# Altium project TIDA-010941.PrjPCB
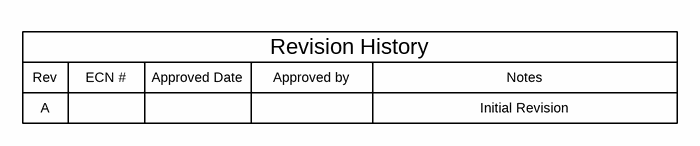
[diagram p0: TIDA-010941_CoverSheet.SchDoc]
CopyrightYear: 2023; PCB_Layout: Boyu Shen; PCB_Rev: E1; PRJ_Customer: Public Release; PRJ_Engineer: Boyu Shen; PRJ_Number: TIDA-010941; PRJ_Title: SASI Smoke Detection w/ Amb. Light Cancellation; SCH_Rev: A; TechSupport: http://www.ti.com/support; TID: TIDA-010941
3 sheets, 116 parts. Net scope: global (net labels, ports and power ports of the same name join across sheets).
Board file: TIDA-010941.PcbDoc
Sheets:
  TIDA-010941_CoverSheet.SchDoc
  TIDA-010941_Hardware.SchDoc
  TIDA-010941_M0L1306.SchDoc

## Sheet TIDA-010941_CoverSheet.SchDoc: Block Diagram / Revision History
size 431 x 279 mm; Date: Not shown in title block; ApprovedBy: Not shown in title block; CheckedBy: Not shown in title block; Author: Not shown in title block; CompanyName: Not shown in title block; DrawnBy: Boyu Shen; Engineer: Not shown in title block; Organization: Not shown in title block; Address1: Not shown in title block; Address2: Not shown in title block; Address3: Not shown in title block; Address4: Not shown in title block; DocumentNumber: 1; Revision: Use project parameter SCH_Rev; SheetNumber: 1; SheetTotal: 3; PageSetup: Record=PageOptions¦CenterHorizontal=True¦CenterVertical=True¦PrintScale=1.00¦XCorrection=1.00¦YCorrection=1.00¦PrintKind=0¦BorderSize=5000000¦LeftOffset=0¦BottomOffset=0¦Orientation=2¦PaperLength=1000¦PaperWidth=1000¦Scale=100¦PaperSource=15¦PrintQuality=600¦MediaType=1¦DitherType=10¦PaperKind=Letter¦PrintScaleMode=1

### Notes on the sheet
- Rev
- A
- ECN #
- Approved Date
- Approved by
- Revision History
- Notes
- Initial Revision

## Sheet TIDA-010941_Hardware.SchDoc: Hardware
size 431 x 279 mm; Date: Not shown in title block; ApprovedBy: Not shown in title block; CheckedBy: Not shown in title block; Author: Not shown in title block; CompanyName: Not shown in title block; DrawnBy: Boyu Shen; Engineer: Not shown in title block; Organization: Not shown in title block; Address1: Not shown in title block; Address2: Not shown in title block; Address3: Not shown in title block; Address4: Not shown in title block; DocumentNumber: 3; Revision: Use project parameter SCH_Rev; SheetNumber: 3; SheetTotal: 3; PageSetup: Record=PageOptions¦CenterHorizontal=True¦CenterVertical=True¦PrintScale=1.00¦XCorrection=1.00¦YCorrection=1.00¦PrintKind=0¦BorderSize=5000000¦LeftOffset=0¦BottomOffset=0¦Orientation=2¦PaperLength=1000¦PaperWidth=1000¦Scale=100¦PaperSource=15¦PrintQuality=600¦MediaType=1¦DitherType=10¦PaperKind=Letter¦PrintScaleMode=1
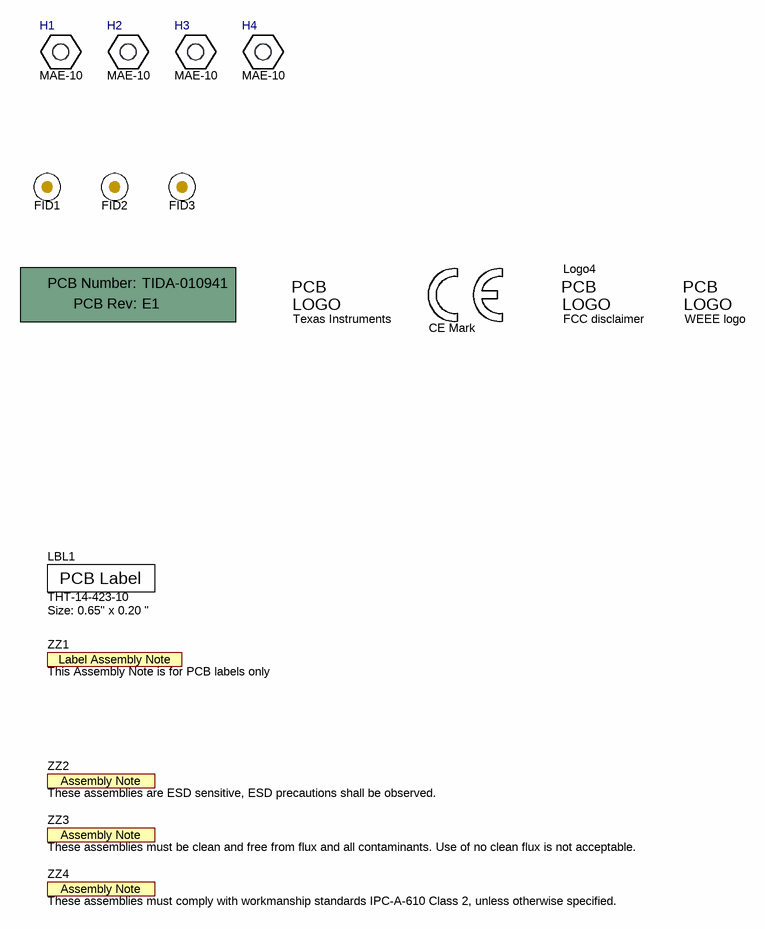
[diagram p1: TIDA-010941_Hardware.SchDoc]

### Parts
!PCB1  Printed Circuit Board  (value not drawn)  (mechanical)
FID1  Fiducial  [Fiducial10-20]  (value not drawn)
FID2  Fiducial  [Fiducial10-20]  (value not drawn)
FID3  Fiducial  [Fiducial10-20]  (value not drawn)
H1  MAE-10  [KY_MAE-10]
H2  MAE-10  [KY_MAE-10]
H3  MAE-10  [KY_MAE-10]
H4  MAE-10  [KY_MAE-10]
LBL1  THT-14-423-10  Note: Size: 0.65" x 0.20 "  [Label_650x200]
Logo1  CE Mark  [CE_Mark_5mm]  (no BOM)
Logo2  Texas Instruments  [TI_Symbol_Overlay_Small]  (no BOM)
Logo3  WEEE logo  [WEEE_Minimum]  (no BOM)
Logo4  FCC disclaimer  [FCC_disclaimer]  (no BOM)
ZZ1  This Assembly Note is for PCB labels only  [AssemblyNoteLabel]  (no BOM)
ZZ2  These assemblies are ESD sensitive, ESD precautions shall be observed.  [AssemblyNote]  (no BOM)
ZZ3  These assemblies must be clean and free from flux and all contaminants. Use of no clean flux is not acceptable.  [AssemblyNote]  (no BOM)
ZZ4  These assemblies must comply with workmanship standards IPC-A-610 Class 2, unless otherwise specified.  [AssemblyNote]  (no BOM)

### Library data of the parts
!PCB1 = CMP-0003618-2: Manufacturer: Any; PartNumber: TIDA-010941
FID1-FID3 = CMP-0077181-1: Fiducial mark.  There is nothing to buy or mount.
H1-H4 = CMP-0077978-1: Spacer Support, Nylon 66; Manufacturer: Kang Yang; CompType: Standoff
LBL1 = CMP-0003625-1: Thermal Transfer Printable Labels, 0.650" W x 0.200" H - 10,000 per roll; Manufacturer: Brady; CompType: Label
Logo1 = CMP-0074844-1: SymbolCreator: a0412235
Logo2 = CMP-0074838-1: Texas Instrument Corporate Signature; SymbolCreator: a0412235; Lib Reference: TI_Logo; Library Reference: Logo
Logo3 = CMP-0074769-1
Logo4 = CMP-0074847-1: FCC_disclaimer
ZZ1 = CMP-0003616-3
ZZ2 = CMP-0077236-1
ZZ3 = CMP-0077237-1
ZZ4 = CMP-0077238-1

## Sheet TIDA-010941_M0L1306.SchDoc: Main Circuit Schematic
size A2; Date: Not shown in title block; ApprovedBy: Not shown in title block; CheckedBy: Not shown in title block; Author: Not shown in title block; CompanyName: Not shown in title block; DrawnBy: Boyu Shen; Engineer: Not shown in title block; Organization: Not shown in title block; Address1: Not shown in title block; Address2: Not shown in title block; Address3: Not shown in title block; Address4: Not shown in title block; DocumentNumber: 1; Revision: Use project parameter SCH_Rev; SheetNumber: 2; SheetTotal: 3; PageSetup: Record=PageOptions¦CenterHorizontal=True¦CenterVertical=True¦PrintScale=0.69¦XCorrection=1.00¦YCorrection=1.00¦PrintKind=0¦BorderSize=5000000¦LeftOffset=0¦BottomOffset=0¦Orientation=2¦PaperLength=1000¦PaperWidth=1000¦Scale=100¦PaperSource=15¦PrintQuality=600¦MediaType=1¦DitherType=10¦PaperKind=Letter¦PrintScaleMode=1
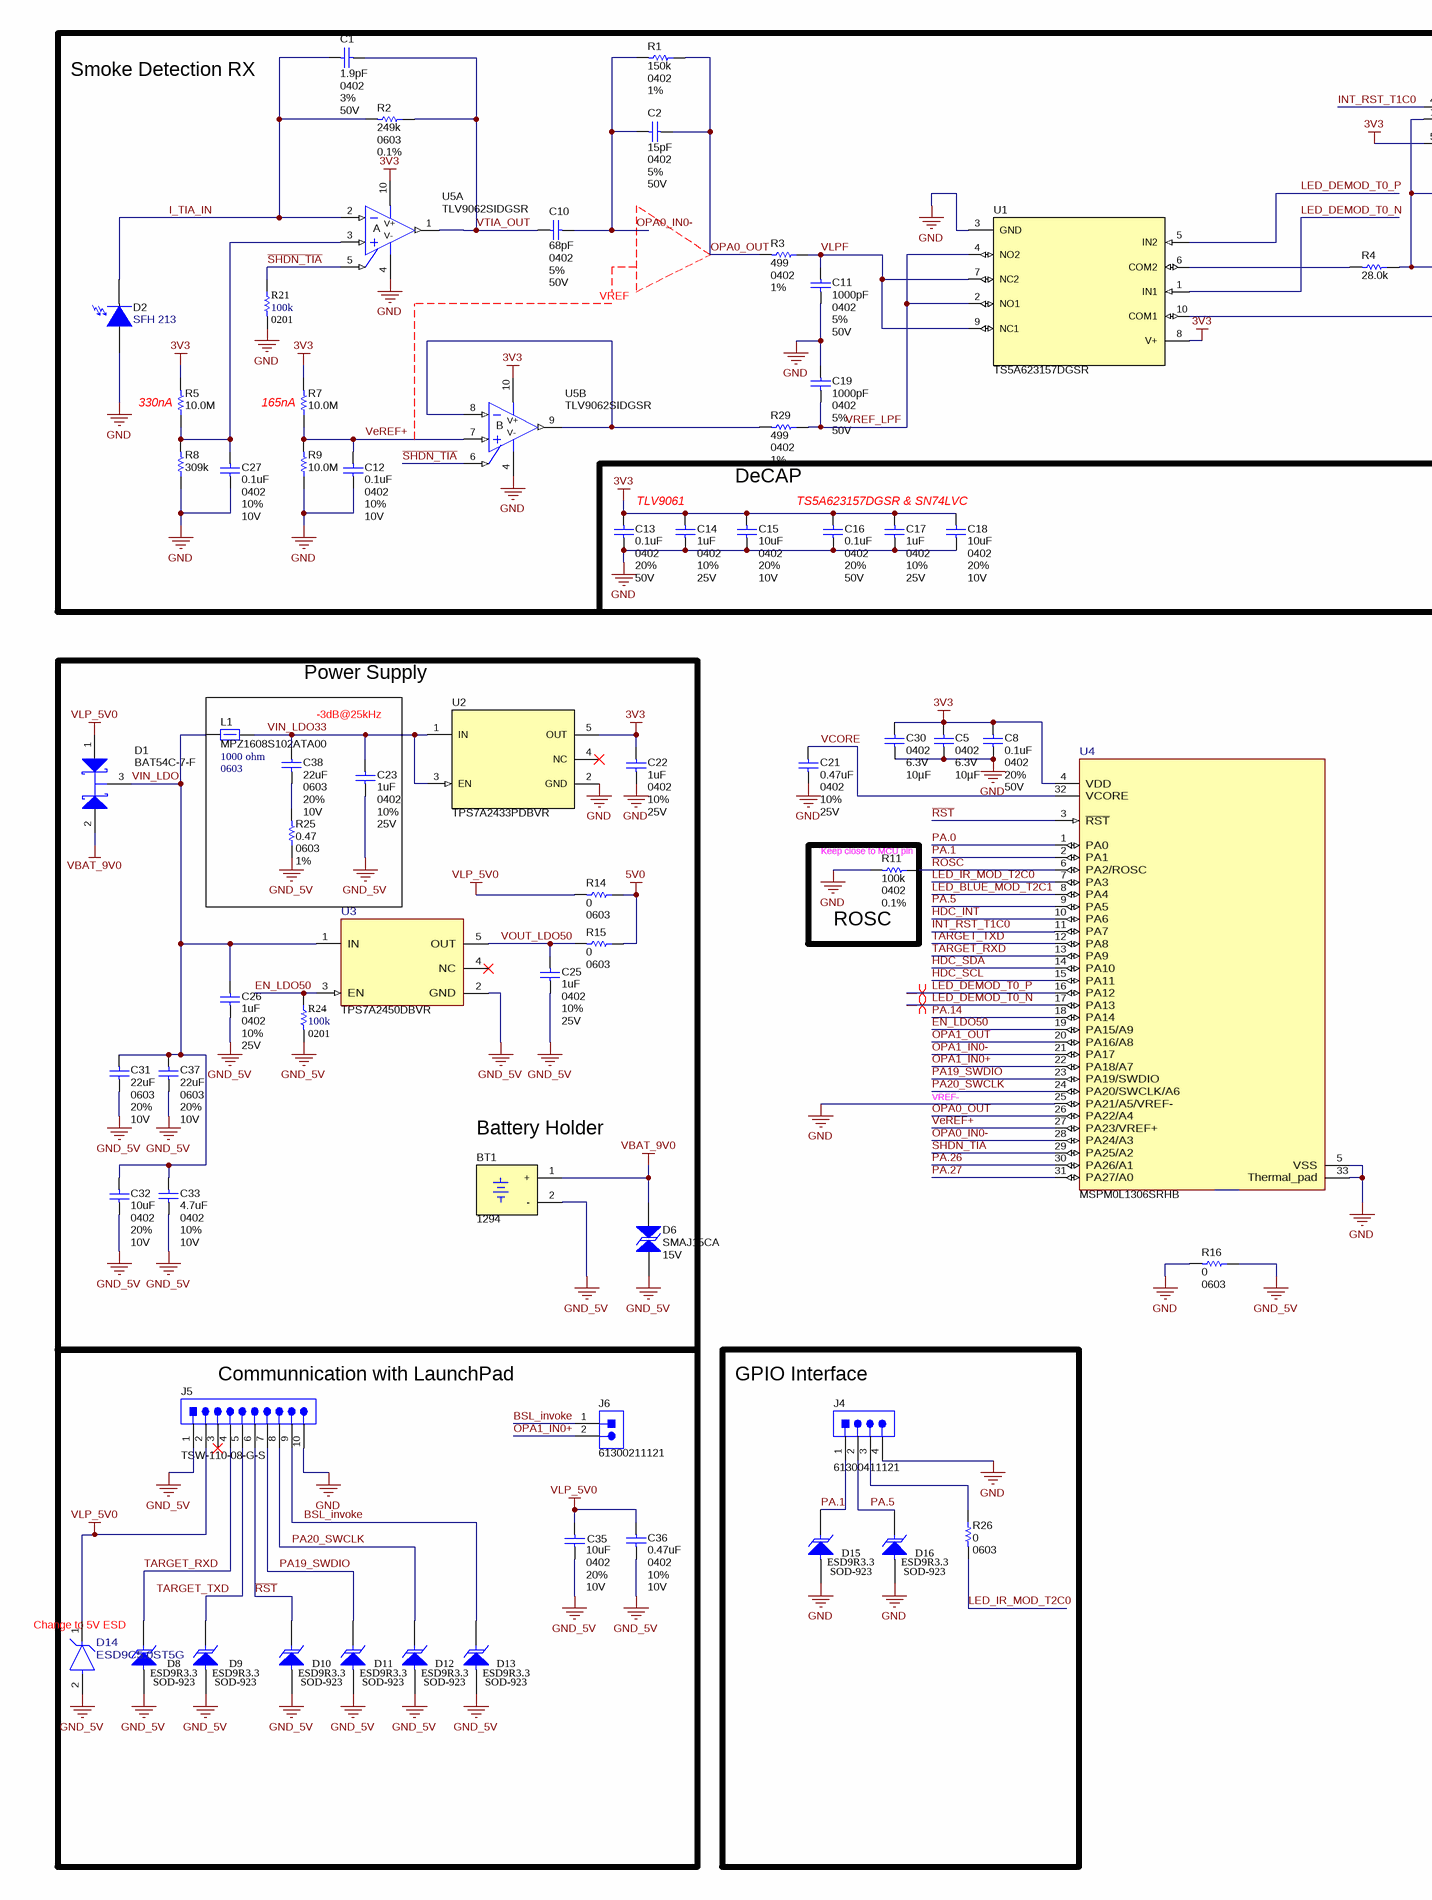
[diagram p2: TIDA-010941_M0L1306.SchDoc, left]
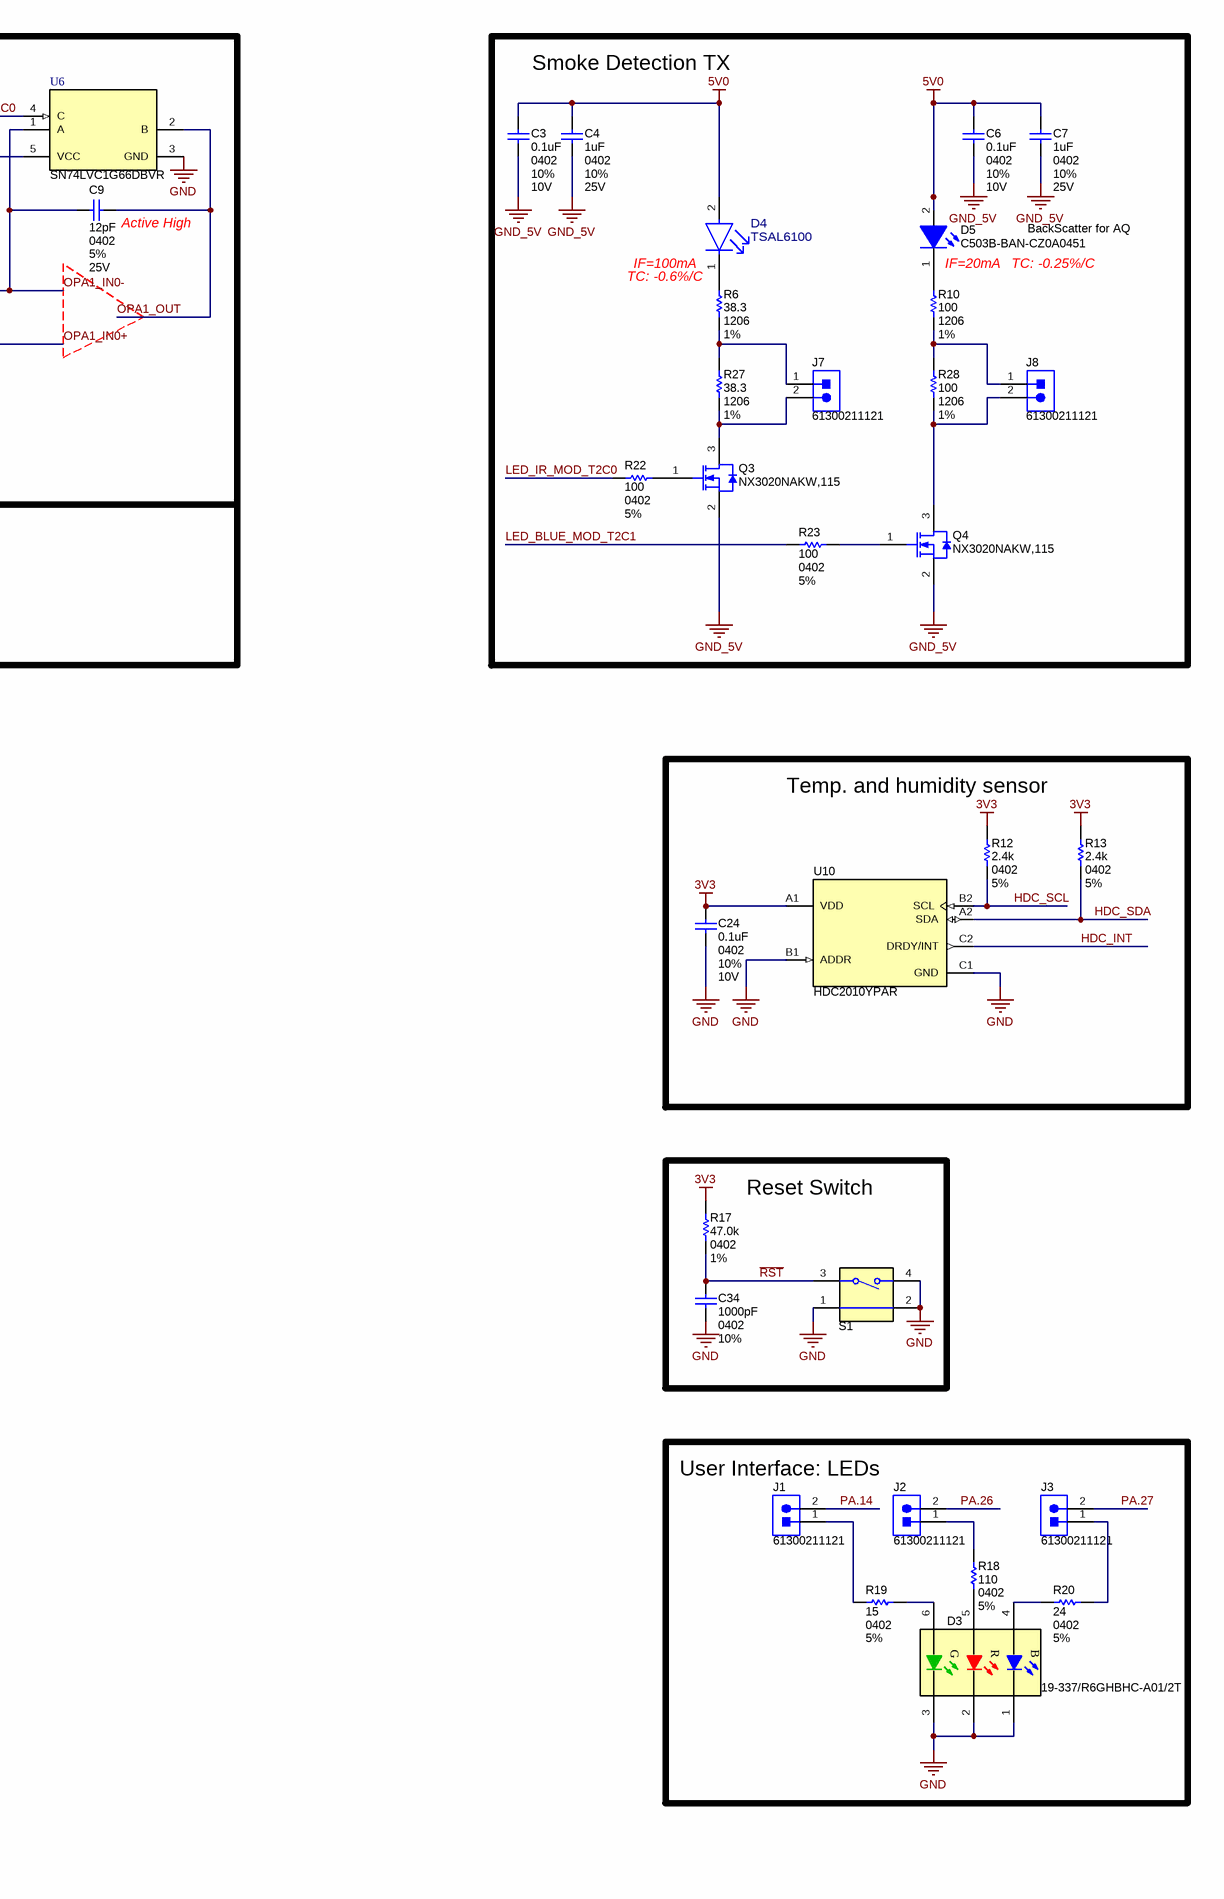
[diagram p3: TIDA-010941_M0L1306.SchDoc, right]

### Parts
BT1  1294  [Keystone_1294]
C1  value 1.9pF  PackageReference: 0402  Tolerance_%: 3%  VDC_V: 50V  [0402L]  (hidden comment: GRM1555C1H1R9WA01D)
C2  value 15pF  PackageReference: 0402  Tolerance_%: 5%  VDC_V: 50V  [0402L]  (hidden comment: GRM1555C1H150JA01D)
C3  value 0.1uF  PackageReference: 0402  Tolerance_%: 10%  VDC_V: 10V  [0402L]  (hidden comment: GRM155R61A104KA01D)
C4  value 1uF  PackageReference: 0402  Tolerance_%: 10%  VDC_V: 25V  [0402L]  (hidden comment: GRM155R61E105KA12D)
C5  PackageReference: 0402  VDC_V: 6.3V  ValueDisplayed: 10µF  [0402_070]  (hidden comment: C0402C106M9PACTU)
C6  value 0.1uF  PackageReference: 0402  Tolerance_%: 10%  VDC_V: 10V  [0402L]  (hidden comment: GRM155R61A104KA01D)
C7  value 1uF  PackageReference: 0402  Tolerance_%: 10%  VDC_V: 25V  [0402L]  (hidden comment: GRM155R61E105KA12D)
C8  value 0.1uF  PackageReference: 0402  Tolerance_%: 20%  VDC_V: 50V  [0402L]  (hidden comment: CMP-0006614-2)
C9  value 12pF  PackageReference: 0402  Tolerance_%: 5%  VDC_V: 25V  [0402L]  (hidden comment: GRM1555C1E120JA01D)
C10  value 68pF  PackageReference: 0402  Tolerance_%: 5%  VDC_V: 50V  [0402L]  (hidden comment: GRM1555C1H680JA01D)
C11  value 1000pF  PackageReference: 0402  Tolerance_%: 5%  VDC_V: 50V  [0402L]  (hidden comment: GRM1555C1H102JA01D)
C12  value 0.1uF  PackageReference: 0402  Tolerance_%: 10%  VDC_V: 10V  [0402L]  (hidden comment: C0402C104K8RACTU)
C13  value 0.1uF  PackageReference: 0402  Tolerance_%: 20%  VDC_V: 50V  [0402L]  (hidden comment: CMP-0006614-2)
C14  value 1uF  PackageReference: 0402  Tolerance_%: 10%  VDC_V: 25V  [0402L]  (hidden comment: GRM155R61E105KA12D)
C15  value 10uF  PackageReference: 0402  Tolerance_%: 20%  VDC_V: 10V  [0402_090S]  (hidden comment: CL05A106MP8NUB8)
C16  value 0.1uF  PackageReference: 0402  Tolerance_%: 20%  VDC_V: 50V  [0402L]  (hidden comment: CMP-0006614-2)
C17  value 1uF  PackageReference: 0402  Tolerance_%: 10%  VDC_V: 25V  [0402L]  (hidden comment: GRM155R61E105KA12D)
C18  value 10uF  PackageReference: 0402  Tolerance_%: 20%  VDC_V: 10V  [0402_090S]  (hidden comment: CL05A106MP8NUB8)
C19  value 1000pF  PackageReference: 0402  Tolerance_%: 5%  VDC_V: 50V  [0402L]  (hidden comment: GRM1555C1H102JA01D)
C21  value 0.47uF  PackageReference: 0402  Tolerance_%: 10%  VDC_V: 25V  [0402L]  (hidden comment: GRM155R61E474KE01D)
C22  value 1uF  PackageReference: 0402  Tolerance_%: 10%  VDC_V: 25V  [0402L]  (hidden comment: GRM155R61E105KA12D)
C23  value 1uF  PackageReference: 0402  Tolerance_%: 10%  VDC_V: 25V  [0402L]  (hidden comment: GRM155R61E105KA12D)
C24  value 0.1uF  PackageReference: 0402  Tolerance_%: 10%  VDC_V: 10V  [0402L]  (hidden comment: GRM155R61A104KA01D)
C25  value 1uF  PackageReference: 0402  Tolerance_%: 10%  VDC_V: 25V  [0402L]  (hidden comment: GRM155R61E105KA12D)
C26  value 1uF  PackageReference: 0402  Tolerance_%: 10%  VDC_V: 25V  [0402L]  (hidden comment: GRM155R61E105KA12D)
C27  value 0.1uF  PackageReference: 0402  Tolerance_%: 10%  VDC_V: 10V  [0402L]  (hidden comment: C0402C104K8RACTU)
C30  PackageReference: 0402  VDC_V: 6.3V  ValueDisplayed: 10µF  [0402_070]  (hidden comment: C0402C106M9PACTU)
C31  value 22uF  PackageReference: 0603  Tolerance_%: 20%  VDC_V: 10V  [0603L]  (hidden comment: GRM187R61A226ME15D)
C32  value 10uF  PackageReference: 0402  Tolerance_%: 20%  VDC_V: 10V  [0402_090S]  (hidden comment: CL05A106MP8NUB8)
C33  value 4.7uF  PackageReference: 0402  Tolerance_%: 10%  VDC_V: 10V  [0402_065L]  (hidden comment: C1005X5R1A475K050BC)
C34  value 1000pF  PackageReference: 0402  Tolerance_%: 10%  [0402L]  (hidden comment: CMP-0006673-2)
C35  value 10uF  PackageReference: 0402  Tolerance_%: 20%  VDC_V: 10V  [0402_090S]  (hidden comment: CL05A106MP8NUB8)
C36  value 0.47uF  PackageReference: 0402  Tolerance_%: 10%  VDC_V: 10V  [0402L]  (hidden comment: GRM155R61A474KE15D)
C37  value 22uF  PackageReference: 0603  Tolerance_%: 20%  VDC_V: 10V  [0603L]  (hidden comment: GRM187R61A226ME15D)
C38  value 22uF  PackageReference: 0603  Tolerance_%: 20%  VDC_V: 10V  [0603L]  (hidden comment: GRM188R61A226ME15D)
D1  BAT54C-7-F  [SOT-23]
D2  SFH 213  [SFH_213]
D3  19-337/R6GHBHC-A01/2T  [19-337_RGB]
D4  TSAL6100  [FP-TSAL6100_RADIAL-MFG]
D5  C503B-BAN-CZ0A0451  [FP-C503B-BAN-CY0Z0451_RADIAL-MFG]
D6  SMAJ15CA  value 15V  [SMA_Bi]
D8  ESD9R3.3  [SOD-923]
D9  ESD9R3.3  [SOD-923]
D10  ESD9R3.3  [SOD-923]
D11  ESD9R3.3  [SOD-923]
D12  ESD9R3.3  [SOD-923]
D13  ESD9R3.3  [SOD-923]
D14  ESD9C5.0ST5G  [FP-ESD9C5.0ST5G_SOD923-MFG]
D15  ESD9R3.3  [SOD-923]
D16  ESD9R3.3  [SOD-923]
J1  61300211121  [WURTH_61300211121]
J2  61300211121  [WURTH_61300211121]
J3  61300211121  [WURTH_61300211121]
J4  61300411121  [WURTH_61300411121]
J5  TSW-110-08-G-S  [Samtec_TSW-110-08-x-S]
J6  61300211121  [WURTH_61300211121]
J7  61300211121  [WURTH_61300211121]
J8  61300211121  [WURTH_61300211121]
L1  MPZ1608S102ATA00  value 1000 ohm  PackageReference: 0603  [0603L]
Q3  NX3020NAKW,115  [SOT-323]
Q4  NX3020NAKW,115  [SOT-323]
R1  value 150k  PackageReference: 0402  Tolerance_%: 1%  [0402L]  (hidden comment: CRCW0402150KFKED)
R2  value 249k  PackageReference: 0603  Tolerance_%: 0.1%  [0603L]  (hidden comment: RG1608P-2493-B-T5)
R3  value 499  PackageReference: 0402  Tolerance_%: 1%  [0402L]  (hidden comment: CRCW0402499RFKED)
R4  ValueDisplayed: 28.0k  [0402L]  (hidden comment: CRCW040228K0FKED)
R5  ValueDisplayed: 10.0M  [0603L]  (hidden comment: RC0603FR-0710ML)
R6  value 38.3  PackageReference: 1206  Tolerance_%: 1%  [1206L]  (hidden comment: ERJ-8ENF38R3V)
R7  ValueDisplayed: 10.0M  [0603L]  (hidden comment: RC0603FR-0710ML)
R8  ValueDisplayed: 309k  [0603L]  (hidden comment: RC0603FR-07309KL)
R9  ValueDisplayed: 10.0M  [0603L]  (hidden comment: RC0603FR-0710ML)
R10  value 100  PackageReference: 1206  Tolerance_%: 1%  [1206L]  (hidden comment: ERJ-8ENF1000V)
R11  value 100k  PackageReference: 0402  Tolerance_%: 0.1%  [0402L]  (hidden comment: RG1005P-104-B-T5)
R12  value 2.4k  PackageReference: 0402  Tolerance_%: 5%  [0402L]  (hidden comment: CRCW04022K40JNED)
R13  value 2.4k  PackageReference: 0402  Tolerance_%: 5%  [0402L]  (hidden comment: CRCW04022K40JNED)
R14  value 0  PackageReference: 0603  [0603L]  (hidden comment: RC0603JR-070RL)
R15  value 0  PackageReference: 0603  [0603L]  (hidden comment: RC0603JR-070RL)
R16  value 0  PackageReference: 0603  [0603L]  (hidden comment: RC0603JR-070RL)
R17  value 47.0k  PackageReference: 0402  Tolerance_%: 1%  [0402L]  (hidden comment: CMP-0026737-1)
R18  value 110  PackageReference: 0402  Tolerance_%: 5%  [0402L]  (hidden comment: CRCW0402110RJNED)
R19  value 15  PackageReference: 0402  Tolerance_%: 5%  [0402L]  (hidden comment: CRCW040215R0JNED)
R20  value 24  PackageReference: 0402  Tolerance_%: 5%  [0402L]  (hidden comment: CRCW040224R0JNED)
R21  value 100k  PackageReference: 0201  [0201L]  (hidden comment: CRCW0201100KFKED)
R22  value 100  PackageReference: 0402  Tolerance_%: 5%  [0402L]  (hidden comment: CRCW0402100RJNED)
R23  value 100  PackageReference: 0402  Tolerance_%: 5%  [0402L]  (hidden comment: CRCW0402100RJNED)
R24  value 100k  PackageReference: 0201  [0201L]  (hidden comment: CRCW0201100KFKED)
R25  value 0.47  PackageReference: 0603  Tolerance_%: 1%  [0603L]  (hidden comment: ERJ-3RQFR47V)
R26  value 0  PackageReference: 0603  [0603L]  (hidden comment: RC0603JR-070RL)
R27  value 38.3  PackageReference: 1206  Tolerance_%: 1%  [1206L]  (hidden comment: ERJ-8ENF38R3V)
R28  value 100  PackageReference: 1206  Tolerance_%: 1%  [1206L]  (hidden comment: ERJ-8ENF1000V)
R29  value 499  PackageReference: 0402  Tolerance_%: 1%  [0402L]  (hidden comment: CRCW0402499RFKED)
S1  CMP-0002328-1  [SW_1188E]  (value not drawn)
U1  TS5A623157DGSR  [DGS0010A_N]
U2  TPS7A2433PDBVR  [DBV0005A_N]
U3  TPS7A2450DBVR  [DBV0005A-MFG]
U4  MSPM0L1306SRHB  [RHB0032N-MFG]
U5  TLV9062SIDGSR  [DGS0010A_N]  (parts A,B of 2)
U6  SN74LVC1G66DBVR  [DBV0005A_L]
U10  HDC2010YPAR  [YPA0006ABAB]

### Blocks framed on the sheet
Smoke Detection RX: C1 C2 C9-C12 C19 C27 D2 R1-R5 R7-R9 R21 R29 U1 U5 U6
Smoke Detection TX: C3 C4 C6 C7 D4 D5 J7 J8 Q3 Q4 R6 R10 R22 R23 R27 R28
DeCAP: C13-C18
Battery Holder: BT1 C22 C25 C26 C31-C33 C37 D1 D6 R14 R15 R24 U2 U3
Power Supply: C23 C38 L1 R25
Temp. and humidity sensor: C24 R12 R13 U10
ROSC: R11
Reset Switch: C34 R17 S1
Communnication with LaunchPad: C35 C36 D8-D14 J5 J6
GPIO Interface: D15 D16 J4 R26
User Interface: LEDs: D3 J1-J3 R18-R20

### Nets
3V3: C5.1 C8.1 C13.1 C14.1 C15.1 C16.1 C17.1 C18.1 C22.1 C24.2 C30.1 R5.2 R7.2 R12.1 R13.1 R17.1 U1.8(V+) U2.5(OUT) U4.4(VDD) U5.10(V+) U6.5(VCC) U10.A1(VDD)
5V0: C3.2 C4.2 C6.2 C7.2 D4.2(ANODE) D5.2(A) R14.1 R15.1
GND: C5.2 C8.2 C11.1 C12.2 C13.2 C14.2 C15.2 C16.2 C17.2 C18.2 C19.2 C21.2 C22.2 C24.1 C27.2 C30.2 C34.2 D2.1(A) D3.1(K) D3.2(K) D3.3(K) D15.2(A) D16.2(A) J4.4 J5.10 R8.1 R9.1 R11.2 R16.2 R21.2 S1.1 S1.2 S1.4 U1.3(GND) U2.2(GND) U4.5(VSS) U4.25(PA21/A5/VREF-) U4.33(Thermal_pad) U5.4(V-) U6.3(GND) U10.B1(ADDR) U10.C1(GND)
GND_5V: BT1.2(-) C3.1 C4.1 C6.1 C7.1 C23.2 C25.2 C26.2 C31.2 C32.2 C33.1 C35.2 C36.1 C37.2 D6.1 D8.2(A) D9.2(A) D10.2(A) D11.2(A) D12.2(A) D13.2(A) D14.2(ANODE) J5.1 Q3.2(S) Q4.2(S) R16.1 R24.2 R25.1 U3.2(GND)
VBAT_9V0: BT1.1(+) D1.2(A2) D6.2
VLP_5V0: C35.1 C36.2 D1.1(A1) D14.1(CATHODE) J5.2 R14.2
BSL_invoke: D13.1(K) J5.9 J6.1
EN_LDO50: R24.1 U3.3(EN) U4.19(PA15/A9)
HDC_INT: U4.10(PA6) U10.C2(DRDY/INT)
HDC_SCL: R12.2 U4.15(PA11) U10.B2(SCL)
HDC_SDA: R13.2 U4.14(PA10) U10.A2(SDA)
I_TIA_IN: C1.2 D2.2(C) R2.2 U5.2(-IN_A)
INT_RST_T1C0: U4.11(PA7) U6.4(C)
LED_BLUE_MOD_T2C1: R23.2 U4.8(PA4)
LED_DEMOD_T0_N: U1.1(IN1) U4.17(PA13)
LED_DEMOD_T0_P: U1.5(IN2) U4.16(PA12)
LED_IR_MOD_T2C0: R22.2 R26.2 U4.7(PA3)
OPA0_IN0-: C2.2 C10.2 R1.2 U4.28(PA24/A3)
OPA0_OUT: C2.1 R1.1 R3.2 U4.26(PA22/A4)
OPA1_IN0+: J6.2 U1.10(COM1) U4.22(PA18/A7)
OPA1_IN0-: C9.1 R4.1 U4.21(PA17) U6.1(A)
OPA1_OUT: C9.2 U4.20(PA16/A8) U6.2(B)
PA19_SWDIO: D11.1(K) J5.7 U4.23(PA19/SWDIO)
PA20_SWCLK: D12.1(K) J5.8 U4.24(PA20/SWCLK/A6)
PA.0: U4.1(PA0)
PA.1: D15.1(K) J4.1 U4.2(PA1)
PA.5: D16.1(K) J4.2 U4.9(PA5)
PA.14: J1.2 U4.18(PA14)
PA.26: J2.2 U4.30(PA26/A1)
PA.27: J3.2 U4.31(PA27/A0)
~{RST}: C34.1 D10.1(K) J5.6 R17.2 S1.3 U4.3(~{RST})
ROSC: R11.1 U4.6(PA2/ROSC)
~{SHDN_TIA}: R21.1 U4.29(PA25/A2) U5.5(~{SHDN_A}) U5.6(~{SHDN_B})
TARGET_RXD: D8.1(K) J5.4 U4.13(PA9)
TARGET_TXD: D9.1(K) J5.5 U4.12(PA8)
VCORE: C21.1 U4.32(VCORE)
VeREF+: C12.1 R7.1 R9.2 U4.27(PA23/VREF+) U5.7(+IN_B)
VIN_LDO: C26.1 C31.1 C32.1 C33.2 C37.1 D1.3(K) L1.2 U3.1(IN)
VIN_LDO33: C23.1 C38.2 L1.1 U2.1(IN) U2.3(EN)
VLPF: C11.2 R3.1 U1.7(NC2) U1.9(NC1)
VOUT_LDO50: C25.1 R15.2 U3.5(OUT)
VREF_LPF: C19.1 R29.1 U1.2(NO1) U1.4(NO2)
VTIA_OUT: C1.1 C10.1 R2.1 U5.1(OUT_A)
NetC27_1: C27.1 R5.1 R8.2 U5.3(+IN_A)
NetC38_1: C38.1 R25.2
NetD3_4: D3.4(A) R20.1
NetD3_5: D3.5(A) R18.2
NetD3_6: D3.6(A) R19.2
NetD4_1: D4.1(CATHODE) R6.1
NetD5_1: D5.1(K) R10.1
NetJ1_1: J1.1 R19.1
NetJ2_1: J2.1 R18.1
NetJ3_1: J3.1 R20.2
NetJ4_3: J4.3 R26.1
NetJ7_1: J7.1 R6.2 R27.1
NetJ7_2: J7.2 Q3.3(D) R27.2
NetJ8_1: J8.1 R10.2 R28.1
NetJ8_2: J8.2 Q4.3(D) R28.2
NetQ3_1: Q3.1(G) R22.1
NetQ4_1: Q4.1(G) R23.1
NetR4_2: R4.2 U1.6(COM2)
NetR29_2: R29.2 U5.8(-IN_B) U5.9(OUT_B)

Not connected (* = marked no-connect by the designer): J5 3*; U2 4(NC)*; U3 4(NC)*

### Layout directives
differential pair: LED_DEMOD_T0_N, LED_DEMOD_T0_P

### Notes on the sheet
- (near C9) Active High
- BackScatter for AQ
- IF=100mA
- TC: -0.6%/C
- IF=20mA
- TC: -0.25%/C
- VREF
- (near R5) 330nA
- (near R7) 165nA
- TLV9061
- TS5A623157DGSR & SN74LVC
- -3dB@25kHz
- (near R11) Keep close to MCU pin
- VREF-
- (near D14) Change to 5V ESD

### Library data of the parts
BT1 = CMP-0003865-1: 9 V Molded Battery Holder, TH; Manufacturer: Keystone; Value: 9 V
C1 = CMP-0080077-1: CAP, CERM, 1.9 pF, 50 V,+/- 3%, C0G/NP0, 0402; Manufacturer: MuRata; TaMin_C: -55°C; Polarized: N; SizeAreaWB_mm2: 3; U/M: EA; TaMax_C: 125°C; SizeZ_mm: 0.6; SizeX_mm: 1; SizeY_mm: 0.5; AEC Category: Q200
C2 = CMP-0006420-2: CAP, CERM, 15 pF, 50 V, +/- 5%, C0G/NP0, 0402; Manufacturer: MuRata; TaMin_C: -55°C; Polarized: N; SizeAreaWB_mm2: 3; Value1: Unknown; U/M: EA; TaMax_C: 125°C; SizeZ_mm: 0.6; SizeX_mm: 1; SizeY_mm: 0.5; AEC Category: Q200
C3 C6 C24 = CMP-0006562-2: CAP, CERM, 0.1 uF, 10 V, +/- 10%, X5R, 0402; Manufacturer: MuRata; TaMin_C: -55°C; Polarized: N; SizeAreaWB_mm2: 3; Value1: Unknown; U/M: EA; TaMax_C: 85°C; SizeZ_mm: 0.6; SizeX_mm: 1; SizeY_mm: 0.5; Cap_F: 100nF; AEC Category: Q200
C4 C7 C14 C17 C22 C23 C25 C26 = CMP-0006608-2: CAP, CERM, 1 uF, 25 V, +/- 10%, X5R, 0402; Manufacturer: MuRata; TaMin_C: -55°C; Polarized: N; SizeAreaWB_mm2: 3; Value1: Unknown; U/M: EA; TaMax_C: 85°C; SizeZ_mm: 0.6; SizeX_mm: 1; SizeY_mm: 0.5; Cap_F: 1µF; AEC Category: Q200
C5 C30 = CMP-0081134-1: CAP, CERM, 10 µF, 6.3 V,+/- 20%, X5R, 0402; Manufacturer: Kemet; TaMin_C: -55°C; ESR_ohm: 1m; Polarized: N; SizeAreaWB_mm2: 3; Value1: 0.001 ohm; U/M: EA; Value: 10uF; TaMax_C: 85°C; SizeZ_mm: 0.7; SizeX_mm: 1; SizeY_mm: 0.5; AEC Category: Q200
C8 C13 C16 = CMP-0006614-2: CAP, CERM, 0.1 uF, 50 V, +/- 20%, X5R, 0402; PartNumber: GRM155R61H104ME14D; Manufacturer: MuRata; Polarized: N; U/M: EA; Cap_F: 100nF; Value1: Unknown; TaMin_C: -55°C; TaMax_C: 85°C; SizeArea_mm2: 0.5; SizeAreaWB_mm2: 3; SizeX_mm: 1; SizeZ_mm: 0.6; AEC Category: Q200
C9 = CMP-0006375-2: CAP, CERM, 12 pF, 25 V, +/- 5%, C0G/NP0, 0402; Manufacturer: MuRata; TaMin_C: -55°C; Polarized: N; SizeAreaWB_mm2: 3; Value1: Unknown; U/M: EA; TaMax_C: 125°C; SizeZ_mm: 0.6; SizeX_mm: 1; SizeY_mm: 0.5; AEC Category: Q200
C10 = CMP-0006485-2: CAP, CERM, 68 pF, 50 V, +/- 5%, C0G/NP0, 0402; Manufacturer: MuRata; TaMin_C: -55°C; Polarized: N; SizeAreaWB_mm2: 3; Value1: Unknown; U/M: EA; TaMax_C: 125°C; SizeZ_mm: 0.6; SizeX_mm: 1; SizeY_mm: 0.5; AEC Category: Q200
C11 C19 = CMP-0006412-2: CAP, CERM, 1000 pF, 50 V, +/- 5%, C0G/NP0, 0402; Manufacturer: MuRata; TaMin_C: -55°C; Polarized: N; SizeAreaWB_mm2: 3; Value1: Unknown; U/M: EA; TaMax_C: 125°C; SizeZ_mm: 0.6; SizeX_mm: 1; SizeY_mm: 0.5; Cap_F: 1nF; AEC Category: Q200
C12 C27 = CMP-0078241-1: CAP, CERM, 0.1 µF, 10 V,+/- 10%, X7R, 0402; Manufacturer: Kemet; TaMin_C: -55°C; Polarized: N; SizeAreaWB_mm2: 3; U/M: EA; TaMax_C: 125°C; SizeZ_mm: 0.6; SizeX_mm: 1; SizeY_mm: 0.5; Cap_F: 100nF; AEC Category: Q200; ValueDisplayed: 0.1µF
C15 C18 C32 C35 = CMP-0084009-1: CAP, CERM, 10 µF, 10 V,+/- 20%, X5R, 0402; Manufacturer: Samsung Electro-Mechanics; TaMin_C: -55°C; ESR_ohm: 1m; Polarized: N; Green_Lifecycle: Active; SizeAreaWB_mm2: 3; Green_REACh: Passed; Value1: 0.001 ohm; U/M: EA; TaMax_C: 85°C; SizeZ_mm: 0.9; SizeX_mm: 1; SizeY_mm: 0.5; Cap_F: 10µF; AEC Category: Q200
C21 = CMP-0064928-2: CAP, CERM, 0.47 uF, 25 V,+/- 10%, X5R, 0402; Manufacturer: MuRata; TaMin_C: -55°C; Polarized: N; SizeAreaWB_mm2: 3; Value1: Unknown; U/M: EA; TaMax_C: 85°C; SizeZ_mm: 0.6; SizeX_mm: 1; SizeY_mm: 0.5; Cap_F: 470nF; AEC Category: Q200
C31 C37 = CMP-0007158-5: CAP, CERM, 22 uF, 10 V, +/- 20%, X5R, 0603; Manufacturer: MuRata; TaMin_C: -55°C; Polarized: N; SizeAreaWB_mm2: 4.68; Value1: Unknown; U/M: EA; TaMax_C: 85°C; SizeZ_mm: 1; SizeX_mm: 1.6; SizeY_mm: 0.8; SizeArea_mm2: 1.28; Cap_F: 22µF; AEC Category: Q200
C33 = CMP-0006268-2: CAP, CERM, 4.7 uF, 10 V, +/- 10%, X5R, 0402; Manufacturer: TDK; TaMin_C: -55°C; ESR_ohm: 3.417m; Polarized: N; SizeAreaWB_mm2: 3; Value1: 0.003417 ohm; U/M: EA; TaMax_C: 85°C; SizeZ_mm: 0.65; SizeX_mm: 1; SizeY_mm: 0.5; Cap_Case: 0402_065; Cap_F: 4.7µF; IRMS_A: 2.7063A; AEC Category: Q200
C34 = CMP-0006673-2: CAP, CERM, 1000 pF, 50 V, +/- 10%, X7R, 0402; PartNumber: GRM155R71H102KA01D; Manufacturer: MuRata; Polarized: N; U/M: EA; Cap_F: 1nF; Value1: Unknown; VDC_V: 50V; TaMin_C: -55°C; TaMax_C: 125°C; SizeArea_mm2: 0.5; SizeAreaWB_mm2: 3; SizeX_mm: 1; SizeZ_mm: 0.6; AEC Category: Q200
C36 = CMP-0006580-2: CAP, CERM, 0.47 uF, 10 V, +/- 10%, X5R, 0402; Manufacturer: MuRata; TaMin_C: -55°C; Polarized: N; SizeAreaWB_mm2: 3; Value1: Unknown; U/M: EA; TaMax_C: 85°C; SizeZ_mm: 0.6; SizeX_mm: 1; SizeY_mm: 0.5; Cap_F: 470nF; AEC Category: Q200
C38 = CMP-0007324-5: CAP, CERM, 22 uF, 10 V, +/- 20%, X5R, 0603; Manufacturer: MuRata; TaMin_C: -55°C; Polarized: N; SizeAreaWB_mm2: 4.68; Value1: Unknown; U/M: EA; TaMax_C: 85°C; SizeZ_mm: 1; SizeX_mm: 1.6; SizeY_mm: 0.8; SizeArea_mm2: 1.28; Cap_F: 22µF; AEC Category: Q200
D1 = CMP-0028453-2: Diode, Schottky, 30 V, 0.2 A, SOT-23; Manufacturer: Diodes Inc.; Io_A: 200mA; Green_Lifecycle: Active; SizeAreaWB_mm2: 14; Vr_V: 30V; Green_REACh: Passed; Value1: 0.2A; TJmax_C: 125°C; Value: 30V; SizeZ_mm: 1.1; SizeX_mm: 2.5; SizeY_mm: 3; Vf_V: 650mV; Value2: 0.65V; SizeArea_mm2: 7.5; AEC Category: Q101
D2 = CMP-0002012-2: Silicon PIN Photodiode, TH; Manufacturer: OSRAM
D3 = CMP-0074720-2: LED, RGB, TH; Manufacturer: Everlight; Io_A: 25mA; Vr_V: 5V; Tjmax_C: 85°C; Angle: 120.0; Ir_A: 50µA; Vf_V: 3.8V
D4 = CMP-0087540-1: High Power Infrared Emitting Diode, 940 nm, GaAlAs, MQW; Manufacturer: Vishay; Tjmax_C: 100°C; Power_TotalModule: 160mW; Vr_V: 5V; Symbol Name: SYM-TSAL6100; Vf_V: 1.35V; Angle: 20°; LambdaP: 940nm
D5 = CMP-0087788-2: Blue 470nm LED Indication - Discrete 3.2V Radial; Manufacturer: Cree; Vr_V: 5V; SizeZ_mm: 10.55mm; Angle: 15°; Vf_V: 3V; Power_TotalModule: 120mW
D6 = CMP-0085006-1: Diode, TVS, Bi, 15 V, 24.4 Vc, 400 W, 16.4 A, SMA (non-polarized); Manufacturer: Littelfuse; RJA_CperW: 120; Vbr_Min: 16.7V; Value1: 24.4V; SizeAreaWB_mm2: 32.368125; Green_Lifecycle: Active; SizeArea_mm2: 13.068125; AEC Category: Q101; SizeX_mm: 5.075; SizeY_mm: 2.575; AEC Qualified: N; Ipp: 16.4A; Ppk: 400W; SizeZ_mm: 2.65; Green_REACh: Incomplete; Vbr_Max: 18.5V
D8-D13 D15 D16 = CMP-0005914-3: Diode, TVS, Uni, 3.3 V, SOD-923; PartNumber: ESD9R3.3ST5G; Manufacturer: ON Semiconductor; Value: 3.3V; SizeZ_mm: 0.4; SizeArea_mm2: 0.6; Ppk: 150mW; Value1: 0.15W; SizeAreaWB_mm2: 3.2; SizeX_mm: 1; AEC Category: Q101
D14 = CMP-0097051-1: ESD Suppressor TVS Uni-Dir 5V 2-Pin SOD-923 T/R; Manufacturer: onsemi; SizeZ_mm: 0.4mm; Cap_F: 6pF; Ciiva Ids: 284495; AEC Qualified: No; Import Ts: 1521864842; TJmax_C: +150°C; Direction: Unidirectional; Number Of Channels: 1; Breakdown Voltage: 11V
J1-J3 J6-J8 = CMP-0054794-2: Header, 2.54 mm, 2x1, Gold, TH; Manufacturer: Wurth Elektronik; Shrouded: N; Gender: Male; Green_REACh: Passed; Pitch_mm: 2.54; Green_Lifecycle: Active; Row_Count: 1; Cert_UL: Y
J4 = CMP-0054798-2: Header, 2.54 mm, 4x1, Gold, TH; Manufacturer: Wurth Elektronik; Pitch_mm: 2.54; Gender: Male; Row_Count: 1; Cert_UL: Y; Shrouded: N
J5 = CMP-0055600-1: Header, 2.54mm, 10x1, Gold, TH; Manufacturer: Samtec; CNHeader: TRUE; Current_A: 6.3A; Shrouded: N; Gender: Male; Cert_CSA: Y; Voltage_V: 550V; Row_Count: 1; Pitch_mm: 2.54; CT: FALSE
L1 = CMP-0003424-2: Ferrite Bead, 1000 ohm @ 100 MHz, 0.8 A, 0603; Manufacturer: TDK; ZTyp@100MHz_Ohm: 1k; SizeAreaWB_mm2: 4.68; DCR_ohm: 0.3; Value1: 0.3 ohm; Imax_A: 800mA; SizeZ_mm: 1; SizeX_mm: 1.6; SizeY_mm: 0.8; Value2: 0.8A; SizeArea_mm2: 1.28
Q3 Q4 = CMP-0000643-2: MOSFET, N-CH, 30 V, 0.18 A, SOT-323; Alternate Manufacturer: None; Manufacturer: Nexperia; SizeZ_mm: 1.1; ChType: N; Value2: 0.34 nC; Value1: 5; VdsMax_V: 30V; SizeX_mm: 2.2; Vgs_V: 20V; Value: 30V; Rdson45_ohm: 5.2; SizeArea_mm2: 4.84; AEC Category: Q101; IdsMax_A: 180mA; SizeAreaWB_mm2: 10.24; QgTyp_nC: 0.34
R1 = CMP-0026021-3: RES, 150 k, 1%, 0.063 W, AEC-Q200 Grade 0, 0402; Manufacturer: Vishay-Dale; Power_W: 63mW; TempCo: 100 ppm/C; EIA_Code: E96; SizeX_mm: 1; SizeY_mm: 0.5; SizeZ_mm: 0.6; Value2: 0.063W; AEC Qualified: Y; VDC_V: 50V; AEC Category: Q200; AEC Grade: 0
R2 = CMP-0023490-3: RES, 249 k, 0.1%, 0.1 W, 0603; Manufacturer: Susumu Co Ltd; Power_W: 100mW; TempCo: 25 ppm/C; U/M: EA; EIA_Code: E192; SizeX_mm: 1.6; SizeY_mm: 0.8; SizeZ_mm: 1; Value2: 0.1W; SizeArea_mm2: 1.28; VDC_V: 75V; AEC Category: Q200
R3 R29 = CMP-0026402-2: RES, 499, 1%, 0.063 W, AEC-Q200 Grade 0, 0402; Manufacturer: Vishay-Dale; Power_W: 63mW; TempCo: 100 ppm/C; Value_Code: 499R; EIA_Code: E96; SizeX_mm: 1; SizeY_mm: 0.5; SizeZ_mm: 0.6; Value2: 0.063W; AEC Qualified: Y; VDC_V: 50V; AEC Category: Q200; AEC Grade: 0
R4 = CMP-0026219-2: RES, 28.0 k, 1%, 0.063 W, AEC-Q200 Grade 0, 0402; Manufacturer: Vishay-Dale; Power_W: 63mW; TempCo: 100 ppm/C; Value_Code: 28k0; Value: 28.0k; EIA_Code: E96; Res_ohm: 28k; SizeX_mm: 1; SizeY_mm: 0.5; SizeZ_mm: 0.6; Value2: 0.063W; AEC Qualified: Y; VDC_V: 50V; AEC Category: Q200; AEC Grade: 0
R5 R7 R9 = CMP-0022747-4: RES, 10.0 M, 1%, 0.1 W, 0603; Manufacturer: Yageo; Power_W: 100mW; TempCo: 100 ppm/C; Value_Code: 10M0; Value: 10.0Meg; EIA_Code: E96; Res_ohm: 10M; SizeX_mm: 1.6; SizeY_mm: 0.8; SizeZ_mm: 1; Value2: 0.1W; SizeArea_mm2: 1.28; AEC Qualified: N; VDC_V: 75V; AEC Category: Q200; SizeAreaWB_mm2: 4.68
R6 R27 = CMP-0017576-3: RES, 38.3, 1%, 0.25 W, AEC-Q200 Grade 0, 1206; Manufacturer: Panasonic; Power_W: 250mW; TempCo: 100 ppm/C; Value_Code: 38R3; EIA_Code: E96; SizeX_mm: 3.2; SizeY_mm: 1.6; SizeZ_mm: 1.35; Value2: 0.25W; SizeArea_mm2: 5.12; AEC Qualified: Y; VDC_V: 200V; AEC Category: Q200; AEC Grade: 0; SizeAreaWB_mm2: 10.92
R8 = CMP-0023016-4: RES, 309 k, 1%, 0.1 W, 0603; Manufacturer: Yageo; Power_W: 100mW; TempCo: 100 ppm/C; Value: 309k; EIA_Code: E96; SizeX_mm: 1.6; SizeY_mm: 0.8; SizeZ_mm: 1; Value2: 0.1W; SizeArea_mm2: 1.28; AEC Qualified: N; VDC_V: 75V; AEC Category: Q200; SizeAreaWB_mm2: 4.68
R10 R28 = CMP-0017282-3: RES, 100, 1%, 0.25 W, AEC-Q200 Grade 0, 1206; Manufacturer: Panasonic; Power_W: 250mW; TempCo: 100 ppm/C; Value_Code: 100R; EIA_Code: E96; SizeX_mm: 3.2; SizeY_mm: 1.6; SizeZ_mm: 1.35; Value2: 0.25W; SizeArea_mm2: 5.12; AEC Qualified: Y; VDC_V: 200V; AEC Category: Q200; AEC Grade: 0; SizeAreaWB_mm2: 10.92
R11 = CMP-0026815-1: RES, 100 k, 0.1%, 0.063 W, 0402; Manufacturer: Susumu Co Ltd; Power_W: 63mW; TempCo: 25 ppm/C; U/M: EA; EIA_Code: E192; SizeX_mm: 1; SizeY_mm: 0.5; SizeZ_mm: 0.6; Value2: 0.063W; AEC Category: Q200
R12 R13 = CMP-0026891-5: RES, 2.4 k, 5%, 0.063 W, AEC-Q200 Grade 0, 0402; Manufacturer: Vishay-Dale; Power_W: 63mW; TempCo: 200 ppm/C; Value_Code: 2k40; EIA_Code: E24; SizeX_mm: 1; SizeY_mm: 0.5; SizeZ_mm: 0.6; Value2: 0.063W; AEC Qualified: Y; VDC_V: 50V; AEC Category: Q200; AEC Grade: 0
R14-R16 R26 = CMP-0025885-5: RES, 0, 5%, 0.1 W, 0603; Manufacturer: Yageo; Power_W: 100mW; TempCo: 200 ppm/C; Value_Code: 0000; EIA_Code: E24; SizeX_mm: 1.6; SizeZ_mm: 1; Value2: 0.1W; SizeArea_mm2: 1.28; AEC Qualified: N; VDC_V: 75V; AEC Category: Q200; SizeY_mm: 0.8; SizeAreaWB_mm2: 4.68
R17 = CMP-0026737-1: RES, 47.0 k, 1%, 0.0625 W, 0402; PartNumber: RC0402FR-0747KL; Manufacturer: Yageo America; Res_ohm: 47k; Value_Code: 47k0; Power_W: 62.5mW; VDC_V: 50V; TempCo: 100 ppm/C; SizeArea_mm2: 0.5; SizeX_mm: 1; SizeZ_mm: 0.6; U/M: EA; AEC Category: Q200; AEC Qualified: N
R18 = CMP-0026829-3: RES, 110, 5%, 0.063 W, AEC-Q200 Grade 0, 0402; Manufacturer: Vishay-Dale; Power_W: 63mW; TempCo: 200 ppm/C; Value_Code: 110R; EIA_Code: E24; SizeX_mm: 1; SizeY_mm: 0.5; SizeZ_mm: 0.6; Value2: 0.063W; AEC Qualified: Y; VDC_V: 50V; AEC Category: Q200; AEC Grade: 0
R19 = CMP-0026843-3: RES, 15, 5%, 0.063 W, AEC-Q200 Grade 0, 0402; Manufacturer: Vishay-Dale; Power_W: 63mW; TempCo: 200 ppm/C; Value_Code: 15R0; EIA_Code: E24; SizeX_mm: 1; SizeY_mm: 0.5; SizeZ_mm: 0.6; Value2: 0.063W; AEC Qualified: Y; VDC_V: 50V; AEC Category: Q200; AEC Grade: 0
R20 = CMP-0026884-3: RES, 24, 5%, 0.063 W, AEC-Q200 Grade 0, 0402; Manufacturer: Vishay-Dale; Power_W: 63mW; TempCo: 200 ppm/C; Value_Code: 24R0; EIA_Code: E24; SizeX_mm: 1; SizeY_mm: 0.5; SizeZ_mm: 0.6; Value2: 0.063W; AEC Qualified: Y; VDC_V: 50V; AEC Category: Q200; AEC Grade: 0
R21 R24 = CMP-0027261-3: RES, 100 k, 1%, 0.05 W, 0201; Manufacturer: Vishay-Dale; Power_W: 50mW; TempCo: 100 ppm/C; EIA_Code: E96; SizeX_mm: 0.6; SizeY_mm: 0.3; SizeZ_mm: 0.26; Value2: 0.05W; SizeArea_mm2: 0.18; AEC Qualified: N; VDC_V: 30V; AEC Category: Q200
R22 R23 = CMP-0026824-3: RES, 100, 5%, 0.063 W, AEC-Q200 Grade 0, 0402; Manufacturer: Vishay-Dale; Power_W: 63mW; TempCo: 200 ppm/C; Value_Code: 100R; EIA_Code: E24; SizeX_mm: 1; SizeY_mm: 0.5; SizeZ_mm: 0.6; Value2: 0.063W; AEC Qualified: Y; VDC_V: 50V; AEC Category: Q200; AEC Grade: 0
R25 = CMP-0022716-3: RES, 0.47, 1%, 0.1 W, AEC-Q200 Grade 0, 0603; Manufacturer: Panasonic; Power_W: 100mW; TempCo: 300 ppm/C; Value_Code: R470; EIA_Code: E96; SizeX_mm: 1.6; SizeY_mm: 0.8; SizeZ_mm: 1; Value2: 0.1W; SizeArea_mm2: 1.28; AEC Qualified: Y; AEC Category: Q200; AEC Grade: 0; SizeAreaWB_mm2: 4.68
S1 = CMP-0002328-1: Switch, SPST, 0.05 A, 12 VDC, SMD; PartNumber: 1188E-1K2-V-TR; Manufacturer: Diptronics; SizeAreaWB_mm2: 53.9; SizeArea_mm2: 27.3; SizeX_mm: 7.8; SizeY_mm: 3.5; VDC_V: 12V; PositionCount: 1; CurrentRating_mA: 50A
U1 = CMP-0074343-1: DUAL 10-Ohm SPDT ANALOG SWITCH WITH UNDERSHOOT/OVERSHOOT VOLTAGE PROTECTION, DGS0010A (VSSOP-10); Alternate Manufacturer: Texas Instruments; SizeAreaWB_mm2: 23.6; U/M: EA; SizeZ_mm: 1.1; SizeX_mm: 4.9; SizeY_mm: 3.0; SizeArea_mm2: 14.7; CompType: IC
U2 = CMP-0083932-1: 1µA, Ultra-Low Iq, 200mA Low-Dropout Regulator in a Small-Size Package, DBV0005A (SOT-23-5); Alternate PartNumber: TPS7A2433PDBVT; Alternate Manufacturer: Texas Instruments; SizeAreaWB_mm2: 14.82; Rating: Catalog; SizeZ_mm: 1.45; SizeX_mm: 2.8; SizeY_mm: 2.9; SizeArea_mm2: 8.12; CompType: IC; AEC Qualified: N; AEC Category: Q200
U3 = CMP-0096923-1: Linear Voltage Regulator IC  1 Output  200mA SOT-23-5; Manufacturer: Texas Instruments; AEC Qualified: No; Standoff Height: 0mm; Accuracy Percentage: 2%; SizeZ_mm: 1.45mm; Number Of Outputs: 1; TJmax_C: +125°C; Max Supply Voltage: 18V; Output Type: Fixed; Nominal Supply Current: 2-15uA; Dropout Voltage: 160mV; Output Voltage: 5V; Min Supply Voltage: 2.4V
U4 = CMP-0093968-1: MSPM0L130x Mixed-Signal Microcontrollers; Manufacturer: Texas Instruments; Number Of Pwm Channels: 8; TJmax_C: +130°C; Interface: I2C,SPI,UART,LIN,IrDA,SMBus; Number Of I2C Channels: 2; Memory Size: 64KBytes; Core Architecture: ARM Cortex-M0+; Number Of Spi Channels: 1; Min Supply Voltage: 1.62V; Ram Size: 4KBytes; Data Bus Width: 32bits; TaMax_C: +125°C; Frequency_Fixed: 32MHz; Memory Type: FLASH; Number Of Adc Channels: 10; Standoff Height: 0mm; AEC Qualified: No; Number Of I/Os: 28; TaMin_C: -40°C; SizeZ_mm: 1mm; Max Supply Voltage: 3.6V; Number Of Timers/Counters: 4
U5 = CMP-0861005-1: 10-MHz, low-noise, RRIO, CMOS operational amplifier for cost-sensitive systems, DGS0010A (VSSOP-10); Alternate Manufacturer: Texas Instruments; SizeZ_mm: 1.1; SizeX_mm: 4.9; SizeArea_mm2: 14.7; Rating: Catalog; AEC Category: Q200; SizeAreaWB_mm2: 23.6; AEC Qualified: N; SizeY_mm: 3; CompType: IC
U6 = CMP-0051071-2: Single Analog Switch, DBV0005A (SOT-23-5); Manufacturer: Texas Instruments; Output Drive (IOL/IOH)(Max)(mA): 32/-32; ICC @ Nom Voltage(Max)(mA): 0.01; VCC(Min)(V): 1.65; Rating: Catalog; Bits(#): 1; tpd @ Nom Voltage(Max)(ns): 2,1.2,0.8,0.6; Logic: True; Output Type: CMOS; Schmitt Trigger: No; Switch Configuration: SPST; Input Type: CMOS/TTL; F @ Nom Voltage(Max)(Mhz): 150; VCC(Max)(V): 5.5; Voltage(Nom)(V): 1.8,2.5,3.3,5; AEC Category: Q200; AEC Qualified: N; CompType: IC; SizeAreaWB_mm2: 14.82; SizeArea_mm2: 8.12; SizeX_mm: 2.8; SizeY_mm: 2.9; SizeZ_mm: 1.45
U10 = CMP-0014223-3: HDC2010 Low Power Humidity and Temperature Digital Sensor, YPA0006ABAB (DSBGA-6); Manufacturer: Texas Instruments; Alternate PartNumber: HDC2010YPAT; SizeX_mm: 1.46; CompType: IC; SizeZ_mm: 0.675; SizeArea_mm2: 2.1316; SizeAreaWB_mm2: 6.0516; U/M: EA

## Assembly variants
001: not fitted BT1 D2 D4 D5 R14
